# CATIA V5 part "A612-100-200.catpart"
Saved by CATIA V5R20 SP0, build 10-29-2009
Part number: A612-100-200
Source: Unknown
Property "A": "30.000"
Property "ARTICLENO": "A612-100-200"
Property "B": "40.000"
Property "BOMINFO": "A612-100-200"
Property "CODE": "A612-100-200"
Property "D": "17.500"
Property "FORM": "A"
Property "L": "200.000"
Property "L1": "45.000"
Property "L2": "110.000"
Property "L3": "0.000"
Property "LINA": "A612-100-200"
Property "NB": "A612-100-200"
Property "NBSYN": "$CODE."
Property "NN": "A612"
Property "NT": "CDI 3357 E-Type Wear Plates, steel and self-lubricating"
Property "SUPPLIER": "CF"
Property "T": "25.000"
Property "W": "100.000"
Bounding box of the stored display mesh (mm): x 0 to 25, y 0 to 200, z 0 to 100
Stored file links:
  C:\Users\Utente\Desktop\3D files A612\A612-100-200.catpart
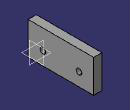
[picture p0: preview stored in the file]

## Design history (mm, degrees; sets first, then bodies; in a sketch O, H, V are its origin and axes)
Body1 "Geometry.1" (main body)
  Solid1 "A612-100-200.catpart": solid without history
